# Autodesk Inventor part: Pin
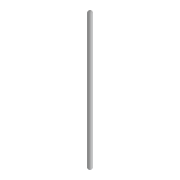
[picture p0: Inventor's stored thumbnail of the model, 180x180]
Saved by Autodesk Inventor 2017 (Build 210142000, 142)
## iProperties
Created: 2015-03
Part Number: Pin
Document SubType Name: Modeling
Designer: Administrator
Density: 1 g/cm^3
Mass: 0.00310887 g
Surface Area: 0.251327 cm^2
Volume: 0.00310887 cm^3
Material: Generic
Appearance: Default
Author: Administrator
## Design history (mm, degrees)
sketch "Sketch1"
  geometry: C1 r 0.25 at (0, 0)
  constraints: 1 centre point
  dimensions: "d0" = 0.5 diameter of C1
extrude "Extrusion1" new body sketch "Sketch1" distance "d1" = 16; taper "d2" = 0 deg
fillet "Fillet1" dims "d3" = 0.25
body "Solid1"
